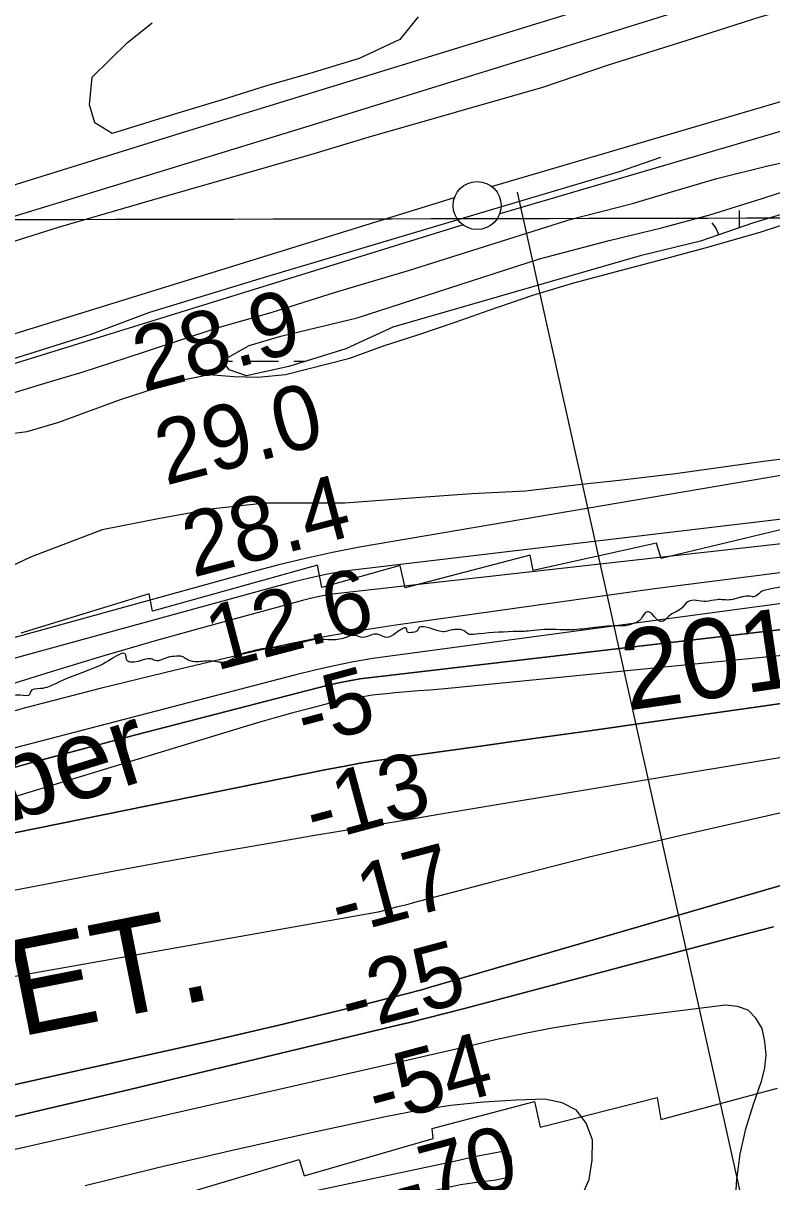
# Model space of a CAD drawing. Extents: x 3324104 to 3361979, y 612876 to 638273.
# Drawn here: x 3358506 to 3359286, y 623368 to 624575 of the extents above; entities that cross this region are included whole.
import ezdxf

# ---------------------------------------------------------------- set-up
doc = ezdxf.new("R2010")
doc.units = 0
for name, color, linetype in [('V-FLOD-BASE', 7, 'Continuous'), ('V-GRID-MAJR', 7, 'Continuous'), ('V-LEVE-TOET', 7, 'Continuous'), ('V-RIVR-EDGE', 7, 'Continuous'), ('V-RIVR-IDEN', 7, 'Continuous'), ('V-RIVR-RANG', 7, 'Continuous'), ('V-ROAD-CNTR', 7, 'Continuous'), ('V-RRAP-RVMT', 7, 'Continuous'), ('V-RRAP-RVMT-IDEN', 7, 'Continuous'), ('V-SITE-VEGE', 7, 'Continuous'), ('V-SURV-LINE', 7, 'Continuous'), ('V-TOPO-DPTH', 7, 'Continuous'), ('V-TOPO-MAJR', 7, 'Continuous'), ('V-TOPO-MINR', 7, 'Continuous'), ('V-TOPO-SHOR', 7, 'Continuous'), ('V-TOPO-WATR', 7, 'Continuous'), ('V-WETL-SWMP', 7, 'Continuous')]:
    doc.layers.add(name, color=color, linetype=linetype)

msp = doc.modelspace()

# ---------------------------------------------------------------- linework, layer by layer
at = {"layer": 'V-FLOD-BASE'}
msp.add_lwpolyline([(3357573.7, 623938.3), (3357694.3, 623971.4), (3357787.7, 624000.3), (3357855.4, 624024.9), (3357917.4, 624046), (3358004.5, 624073.5), (3358209.5, 624137.6), (3358342.7, 624180.5), (3358480, 624220.7), (3358576.2, 624250.9), (3358637.5, 624274.1), (3358756.1, 624310.1), (3358978.5, 624376.3), (3359127, 624420.6), (3359170.2, 624435.4)], dxfattribs=at)
at = {"layer": 'V-GRID-MAJR'}
msp.add_spline([(3328210, 624318.2), (3333474, 624325.5), (3338738.1, 624333.5), (3344002.2, 624342.3), (3349266.2, 624351.9), (3354530.3, 624362.2), (3359794.3, 624373.3)], degree=3, dxfattribs=at)
at = {"layer": 'V-LEVE-TOET'}
for points in [[(3359793.5, 624738.8), (3359769, 624731.3), (3359688.9, 624701.1), (3359550.8, 624665.1), (3359476.2, 624641.2), (3359417.7, 624623.6), (3359352.1, 624603.8), (3359273.3, 624581.3), (3359196, 624556.7), (3359115.1, 624531.3), (3359046.8, 624508.1), (3358864.8, 624455.9), (3358808.3, 624439), (3358629.2, 624387.6), (3358542, 624362.2), (3358457, 624335.5), (3358284.8, 624279.9), (3358184.4, 624245.4), (3358102.8, 624217.3), (3358017.1, 624190.5), (3357952.9, 624172.9), (3357881.1, 624150.3), (3357810.7, 624127.1)], [(3358479, 624185), (3358527.1, 624199.8), (3358568.2, 624211.8), (3358612.9, 624226.5), (3358635.2, 624233.6), (3358668.6, 624244.8), (3358707.7, 624257.5), (3358764.1, 624273.7), (3358831.1, 624294.8), (3358907, 624317.4), (3359076.5, 624370.9), (3359140.6, 624387.1), (3359177.6, 624398.4), (3359228.4, 624413.2), (3359281.4, 624426.6), (3359311.4, 624433)]]:
    msp.add_lwpolyline(points, dxfattribs=at)
at = {"layer": 'V-RIVR-EDGE'}
msp.add_spline([(3359795.1, 624016.8), (3359789.3, 624017.3), (3359775.9, 624016.6), (3359757.2, 624013.5), (3359746.3, 624008.2), (3359732.2, 624007.9), (3359730.4, 624010), (3359728, 624012.1), (3359719.2, 624015.3), (3359708.9, 624015), (3359699.4, 624012.9), (3359694.1, 624014), (3359689.9, 624019.3), (3359671.6, 624018.6), (3359656.8, 624018.7), (3359645.9, 624019.4), (3359641.6, 624018), (3359635.7, 624018), (3359629, 624018.7), (3359625.4, 624017.7), (3359622.6, 624015.9), (3359617.7, 624018.4), (3359614.2, 624018.1), (3359610.6, 624015.6), (3359604.6, 624013.9), (3359595.5, 624015.6), (3359584.6, 624016.7), (3359572.2, 624017.8), (3359546.5, 624016.5), (3359518.3, 624014.1), (3359492.9, 624011), (3359467.9, 624006.1), (3359449.9, 624003.7), (3359441.8, 624003.3), (3359440, 624000.2), (3359435.1, 623999.1), (3359430.9, 623999.1), (3359426.3, 624001.3), (3359420.7, 623999.9), (3359418.5, 623997.8), (3359412.9, 623997.8), (3359403.4, 623999.2), (3359387.5, 623996.8), (3359379.4, 623994.3), (3359374.1, 623986.6), (3359371.6, 623982.4), (3359366.3, 623980.3), (3359359.3, 623979.9), (3359344.8, 623973.3), (3359335, 623971.5), (3359325.1, 623970.1), (3359313.8, 623976.2), (3359306.4, 623982.2), (3359301.9, 623987.1), (3359291.3, 623986.8), (3359279.3, 623984.4), (3359273.7, 623981.9), (3359267, 623977.3), (3359261.3, 623978.1), (3359255.7, 623977.4), (3359251.1, 623976.3), (3359243, 623974.2), (3359228.6, 623974.3), (3359217.3, 623972.5), (3359198.2, 623972.2), (3359192.2, 623965.9), (3359178.1, 623956.8), (3359170.7, 623951.5), (3359167.5, 623952.6), (3359164.7, 623955), (3359158.4, 623961.4), (3359155.9, 623961.8), (3359149.6, 623954.4), (3359141.5, 623949.5), (3359136.2, 623947.7), (3359123.5, 623947), (3359098.5, 623945), (3359077.3, 623942.9), (3359044.5, 623943), (3359031.8, 623941.6), (3359016, 623941), (3358974.8, 623938.2), (3358969.1, 623938.6), (3358965.2, 623941.8), (3358956.8, 623943.2), (3358951.2, 623942.5), (3358945.9, 623941.1), (3358933.2, 623943.3), (3358922.3, 623946.1), (3358918, 623945.1), (3358916.6, 623942.3), (3358911.7, 623940.2), (3358905.7, 623941.2), (3358905.3, 623943.7), (3358894.1, 623939.9), (3358884.5, 623934.9), (3358876.4, 623937.8), (3358872.9, 623938.5), (3358859.5, 623935), (3358851.1, 623937.1), (3358839.1, 623934), (3358822.9, 623932.6), (3358809.8, 623932.7), (3358783.7, 623926), (3358762.2, 623924), (3358742.8, 623920.5), (3358726.3, 623914.5), (3358716.4, 623909.3), (3358700.9, 623910.4), (3358684.3, 623909.7), (3358675.2, 623912.6), (3358672, 623914.7), (3358662.8, 623915.1), (3358657.9, 623914.7), (3358643.1, 623910.9), (3358638.9, 623912.6), (3358635.7, 623912.7), (3358618.8, 623909.2), (3358613.5, 623911.3), (3358612.8, 623913.8), (3358612.1, 623917.3), (3358598, 623912.7), (3358575.4, 623901.5), (3358539.1, 623886.8), (3358523.6, 623881.6), (3358513, 623878.4), (3358512.6, 623876), (3358502.4, 623874.9), (3358488.3, 623871.4), (3358468.9, 623862.3), (3358449.5, 623848.6), (3358433.3, 623838.8), (3358414.2, 623829.7), (3358401.2, 623829), (3358394.5, 623831.1), (3358393.4, 623834.3), (3358394.1, 623838.9), (3358393.4, 623842.1), (3358391.7, 623843.1), (3358389.2, 623843.1), (3358388.9, 623837.9), (3358385.3, 623837.9), (3358382.9, 623833.3), (3358381.1, 623829.1), (3358377.9, 623826.3), (3358373, 623828), (3358366.6, 623827.7), (3358362.4, 623823.8), (3358357.4, 623818.9), (3358350, 623817.5), (3358338.4, 623811.9), (3358324.6, 623804.9), (3358314.1, 623802.8), (3358302.1, 623799), (3358298.9, 623793.7), (3358291.8, 623793.3), (3358284.4, 623793), (3358276, 623792.3), (3358270, 623787.4), (3358261.9, 623780), (3358253.4, 623777.2), (3358241.4, 623775.1), (3358222.7, 623771), (3358210.7, 623766.4), (3358198.7, 623761.9), (3358192, 623752), (3358185.7, 623745.3), (3358171.6, 623742.9), (3358161.7, 623736.2), (3358141.9, 623726.4), (3358128.5, 623723.3), (3358116.5, 623720.8), (3358097.5, 623717), (3358087.3, 623715.6), (3358076.7, 623714.2), (3358064.4, 623711.8), (3358053.1, 623709), (3358034, 623701.7), (3358000.5, 623685.5), (3357981.1, 623681.4), (3357961.4, 623677.9), (3357943.4, 623676.2), (3357922.6, 623674.1), (3357909.2, 623666.7), (3357896.5, 623659), (3357880.3, 623648.1), (3357868.3, 623637.2), (3357853.4, 623620), (3357846.7, 623608.4), (3357833.3, 623593.3), (3357819.5, 623579.2)], degree=3, dxfattribs=at)
at = {"layer": 'V-RIVR-RANG'}
msp.add_line((3359020.3, 624399.2), (3359276.9, 623247.4), dxfattribs=at)
at = {"layer": 'V-ROAD-CNTR'}
msp.add_lwpolyline([(3359791, 624815.2), (3359721.2, 624794.2), (3359118.5, 624598.3), (3358677.7, 624463), (3358086.3, 624278.8), (3357533.4, 624100.8), (3357044.6, 623937.5)], dxfattribs=at)
at = {"layer": 'V-RRAP-RVMT'}
for p, q in [((3359300.8, 624048.6), (3359170.3, 624017.4)), ((3359165.7, 624033.3), (3359036.9, 624004.8)), ((3359170.3, 624017.4), (3359165.7, 624033.3)), ((3359034, 624020.7), (3358903.7, 623986.6)), ((3359036.9, 624004.8), (3359034, 624020.7)), ((3358812.4, 624010.4), (3358640.4, 623962.2)), ((3358816.8, 623987.2), (3358812.4, 624010.4)), ((3358898.3, 624009.9), (3358816.8, 623987.2)), ((3358903.7, 623986.6), (3358898.3, 624009.9)), ((3358636.7, 623980.5), (3358503.2, 623939.3)), ((3358640.4, 623962.2), (3358636.7, 623980.5)), ((3359170.2, 623432.5), (3359291.6, 623465.3)), ((3358931.7, 623423.2), (3359038.5, 623451.3)), ((3359038.5, 623451.3), (3359044.2, 623424.7)), ((3359044.2, 623424.7), (3359166.3, 623455.6)), ((3359166.3, 623455.6), (3359170.2, 623432.5)), ((3358932.9, 623412.8), (3358931.7, 623423.2)), ((3358798.3, 623373.8), (3358932.9, 623412.8)), ((3358680.3, 623357.1), (3358793.2, 623391)), ((3358793.2, 623391), (3358798.3, 623373.8))]:
    msp.add_line(p, q, dxfattribs=at)
at = {"layer": 'V-SITE-VEGE'}
for p, q in [((3359273.7, 624357.4), (3359323.3, 624373.6)), ((3359216.4, 624341.1), (3359273.7, 624357.4)), ((3359167.4, 624327.7), (3359216.4, 624341.1)), ((3359129, 624317.8), (3359167.4, 624327.7)), ((3359079.4, 624304.4), (3359129, 624317.8)), ((3359036.8, 624291.7), (3359079.4, 624304.4)), ((3358991.3, 624276.2), (3359036.8, 624291.7)), ((3358955.7, 624263.5), (3358991.3, 624276.2)), ((3358918, 624250.8), (3358955.7, 624263.5)), ((3358880.9, 624238.8), (3358918, 624250.8)), ((3358846, 624226.1), (3358880.9, 624238.8)), ((3358778.9, 624209.1), (3358846, 624226.1)), ((3358667, 624202.5), (3358699.2, 624208.9)), ((3358699.2, 624208.9), (3358725.1, 624206.9)), ((3358725.1, 624206.9), (3358750.2, 624206.2)), ((3358750.2, 624206.2), (3358778.9, 624209.1)), ((3358606.9, 624182.8), (3358667, 624202.5)), ((3358542.6, 624159.5), (3358606.9, 624182.8)), ((3358509.8, 624149.6), (3358542.6, 624159.5)), ((3358432.2, 624140.3), (3358509.8, 624149.6)), ((3359333.1, 624125.4), (3359277.1, 624118.2)), ((3359277.1, 624118.2), (3359185.5, 624105.4)), ((3359129.6, 624098.9), (3359084.2, 624093.9)), ((3359185.5, 624105.4), (3359129.6, 624098.9)), ((3358973, 624084.5), (3358910.1, 624080.1)), ((3359028.9, 624087.4), (3358973, 624084.5)), ((3359084.2, 624093.9), (3359028.9, 624087.4)), ((3358757.6, 624074.8), (3358703.8, 624069)), ((3358840.8, 624075), (3358757.6, 624074.8)), ((3358910.1, 624080.1), (3358840.8, 624075)), ((3358703.8, 624069), (3358647.8, 624059.1)), ((3358647.8, 624059.1), (3358587.7, 624047)), ((3358587.7, 624047), (3358513, 624018.8)), ((3358513, 624018.8), (3358466.2, 623996.3))]:
    msp.add_line(p, q, dxfattribs=at)
msp.add_lwpolyline([(3358917, 624581.8), (3358898.2, 624558.1), (3358855.7, 624538.4), (3358807.6, 624523.6), (3358758.1, 624509.5), (3358712.8, 624495.4), (3358666.8, 624481.4), (3358598.4, 624460.2), (3358580.3, 624471.3), (3358574.6, 624490.2), (3358577.3, 624518.8), (3358614.2, 624555.2), (3358640, 624575.5)], dxfattribs=at)
at = {"layer": 'V-SURV-LINE'}
for points in [[(3358993.6, 624405.1), (3359793.8, 624640.4)], [(3359793.8, 624609.2), (3359002.1, 624376.4)], [(3358112.8, 624132.9), (3358955.1, 624393.5)], [(3358964, 624364.9), (3358121.7, 624104.3)]]:
    msp.add_lwpolyline(points, dxfattribs=at)
msp.add_circle((3358978.6, 624385.1), 25, dxfattribs=at)
at = {"layer": 'V-TOPO-DPTH'}
for points in [[(3359795.1, 624002), (3359795, 624064.7), (3359704.9, 624052.9), (3359677.3, 624049.3), (3359649.7, 624045.9), (3359622.1, 624042.6), (3359594.5, 624039.3), (3359487.4, 624027.1), (3359163.3, 623985.8), (3358894, 623947.9), (3358857.7, 623942.3), (3358821.4, 623936.1), (3358785.3, 623928.8), (3358749.3, 623920.9), (3358664.1, 623901), (3358585.8, 623881.8), (3358507.8, 623861.6), (3358430.3, 623839.8)], [(3358412.2, 623776.3), (3358517.4, 623805.4), (3358622.8, 623833.5), (3358812.6, 623882.5), (3358823.5, 623885.2), (3358834.4, 623887.6), (3358845.3, 623889.8), (3358856.3, 623891.8), (3359563.8, 623974.6), (3359588.7, 623977.3), (3359613.5, 623980.1), (3359646.5, 623983.9), (3359654.9, 623984.9), (3359663.3, 623985.9), (3359671.6, 623986.9), (3359680, 623987.9), (3359795.1, 624002)], [(3358412.2, 623776.3), (3358517.4, 623805.4), (3358622.8, 623833.5), (3358812.6, 623882.5), (3358823.5, 623885.2), (3358834.4, 623887.6), (3358845.3, 623889.8), (3358856.3, 623891.8), (3359563.8, 623974.6), (3359588.7, 623977.3), (3359613.5, 623980.1), (3359646.5, 623983.9), (3359654.9, 623984.9), (3359663.3, 623985.9), (3359671.6, 623986.9), (3359680, 623987.9), (3359795.1, 624002)], [(3359795.1, 624002), (3359795.3, 623935.2), (3359780.5, 623933.5), (3359754.9, 623930.4), (3359729.3, 623927.1), (3359693.8, 623922.4), (3359686, 623921.4), (3359678.1, 623920.3), (3359670.2, 623919.2), (3359662.4, 623918.1), (3359158.6, 623846.6), (3359098.2, 623838.1), (3359037.8, 623829.6), (3358977.4, 623821.1), (3358891.8, 623809.2), (3358874.2, 623806.6), (3358856.6, 623803.8), (3358839.1, 623800.6), (3358821.6, 623797.2), (3358450, 623721.8)], [(3358450, 623721.8), (3358821.6, 623797.2), (3358839.1, 623800.6), (3358856.6, 623803.8), (3358874.2, 623806.6), (3358891.8, 623809.2), (3358977.4, 623821.1), (3359037.8, 623829.6), (3359098.2, 623838.1), (3359158.6, 623846.6), (3359662.4, 623918.1), (3359670.2, 623919.2), (3359678.1, 623920.3), (3359686, 623921.4), (3359693.8, 623922.4), (3359729.3, 623927.1), (3359754.9, 623930.4), (3359780.5, 623933.5), (3359795.3, 623935.2), (3359795.5, 623861.1)], [(3359795.5, 623861.1), (3359731.4, 623849.4), (3359713.5, 623846), (3359695.7, 623842.4), (3359677.9, 623838.7), (3359660.1, 623834.8), (3359194.2, 623729.2), (3359144, 623717.5), (3359093.9, 623705.5), (3359043.9, 623692.9), (3358994, 623680), (3358913.5, 623658.7), (3358903.9, 623656.1), (3358894.4, 623653.7), (3358884.8, 623651.2), (3358875.3, 623648.8), (3358126, 623516.1)], [(3359795.5, 623861.1), (3359731.4, 623849.4), (3359713.5, 623846), (3359695.7, 623842.4), (3359677.9, 623838.7), (3359660.1, 623834.8), (3359194.2, 623729.2), (3359144, 623717.5), (3359093.9, 623705.5), (3359043.9, 623692.9), (3358994, 623680), (3358913.5, 623658.7), (3358903.9, 623656.1), (3358894.4, 623653.7), (3358884.8, 623651.2), (3358875.3, 623648.8), (3358126, 623516.1)], [(3358072.6, 623374.6), (3358704.8, 623515.3), (3358740.7, 623523.5), (3358776.6, 623531.8), (3358812.4, 623540.5), (3358848.1, 623549.4), (3358910.3, 623565.1), (3358914.9, 623566.3), (3358919.5, 623567.5), (3358924, 623568.8), (3358928.6, 623570.1), (3359598.2, 623764.2)], [(3358072.6, 623374.6), (3358704.8, 623515.3), (3358740.7, 623523.5), (3358776.6, 623531.8), (3358812.4, 623540.5), (3358848.1, 623549.4), (3358910.3, 623565.1), (3358914.9, 623566.3), (3358919.5, 623567.5), (3358924, 623568.8), (3358928.6, 623570.1), (3359598.2, 623764.2)], [(3359287.4, 623633.2), (3359253.8, 623624.8), (3358965.5, 623548.4), (3358946.4, 623543.4), (3358927.2, 623538.5), (3358908, 623533.7), (3358888.7, 623529.1), (3358616.7, 623464), (3358522.9, 623441.8), (3358429, 623419.8)], [(3358429, 623419.8), (3358522.9, 623441.8), (3358616.7, 623464), (3358888.7, 623529.1), (3358908, 623533.7), (3358927.2, 623538.5), (3358946.4, 623543.4), (3358965.5, 623548.4), (3359253.8, 623624.8), (3359287.4, 623633.2)]]:
    msp.add_lwpolyline(points, dxfattribs=at)
at = {"layer": 'V-TOPO-MAJR'}
for points in [[(3359585.2, 624153), (3358855.9, 624029.1), (3358827.8, 624023.5), (3358799.9, 624017.4), (3358772.1, 624010.5), (3358744.4, 624003.3), (3358016.3, 623802.3)], [(3359247.6, 623343.1), (3359249.3, 623370), (3359252.8, 623396.6), (3359258.8, 623422.8), (3359266.5, 623448.6), (3359275, 623472.4), (3359278.3, 623486.1), (3359279.8, 623499.9), (3359278.6, 623513.7), (3359275.6, 623527.5), (3359269.1, 623538.3), (3359260.9, 623546.4), (3359250.1, 623550.4), (3359237.6, 623551.6), (3359120.5, 623537.3), (3359089.6, 623533), (3359058.9, 623528.1), (3359028.3, 623522.1), (3358997.8, 623515.5), (3358967.4, 623508.4), (3358937.1, 623501.4), (3358906.7, 623494.4), (3358876.2, 623487.5), (3358088.9, 623308.7)]]:
    msp.add_lwpolyline(points, dxfattribs=at)
at = {"layer": 'V-TOPO-MINR'}
for points in [[(3359794.9, 624093.1), (3359672.5, 624075.8), (3359658.2, 624073.8), (3359643.8, 624071.9), (3359629.5, 624070.1), (3359615.1, 624068.4), (3358824.9, 623979.8), (3358817.8, 623978.4), (3358810.7, 623976.9), (3358803.6, 623975.2), (3358796.6, 623973.4), (3358699.8, 623947.1), (3358644.6, 623931.8), (3358589.5, 623915.9), (3358534.6, 623899.3), (3358479.8, 623882.2), (3357966.8, 623718.6), (3357954, 623714.4), (3357941.2, 623710.1), (3357928.5, 623705.8), (3357915.8, 623701.3), (3357248, 623461.7)], [(3359594.4, 624093.6), (3358840.4, 624004.2), (3358822.8, 624000.8), (3358805.3, 623997.1), (3358787.8, 623992.9), (3358770.4, 623988.4), (3358452.4, 623901.3)], [(3359795, 624064.7), (3359704.9, 624052.9), (3359677.3, 624049.3), (3359649.7, 624045.9), (3359622.1, 624042.6), (3359594.5, 624039.3), (3359487.4, 624027.1), (3359163.3, 623985.8), (3358894, 623947.9), (3358857.7, 623942.3), (3358821.4, 623936.1), (3358785.3, 623928.8), (3358749.3, 623920.9), (3358664.1, 623901), (3358585.8, 623881.8), (3358507.8, 623861.6), (3358430.3, 623839.8)], [(3359795.1, 624036.4), (3359737.8, 624029.3), (3359696.7, 624024.3), (3358870, 623913.1), (3358849.8, 623909.4), (3358829.6, 623905.4), (3358809.6, 623900.8), (3358789.6, 623895.9), (3358137.7, 623726.6), (3358106.6, 623718.2), (3358075.7, 623709.6), (3358044.8, 623700.4), (3358014.1, 623690.9), (3357983.5, 623681), (3357953, 623670.8), (3357922.6, 623660.3), (3357892.3, 623649.4), (3357881.3, 623645.4), (3357845.6, 623632.3), (3357809.9, 623618.9), (3357774.4, 623605.4), (3357738.9, 623591.6), (3357198, 623379.8)], [(3359795.2, 623967.6), (3359722.4, 623958.3), (3358941.5, 623881.2), (3358929.4, 623880.2), (3358917.4, 623879.2), (3358905.3, 623878.2), (3358893.2, 623877.1), (3358884.1, 623876.3), (3358876.6, 623875.6), (3358869.1, 623874.7), (3358861.5, 623873.6), (3358854, 623872.5), (3358842.6, 623870.5), (3358839.1, 623869.9), (3358837.4, 623869.5), (3358835.6, 623869.1), (3358804.1, 623861), (3358786.7, 623856.4), (3358769.3, 623851.6), (3358752, 623846.7), (3358734.7, 623841.5), (3357991.5, 623614.9)], [(3359795.3, 623935.2), (3359780.5, 623933.5), (3359754.9, 623930.4), (3359729.3, 623927.1), (3359693.8, 623922.4), (3359686, 623921.4), (3359678.1, 623920.3), (3359670.2, 623919.2), (3359662.4, 623918.1), (3359158.6, 623846.6), (3359098.2, 623838.1), (3359037.8, 623829.6), (3358977.4, 623821.1), (3358891.8, 623809.2), (3358874.2, 623806.6), (3358856.6, 623803.8), (3358839.1, 623800.6), (3358821.6, 623797.2), (3358450, 623721.8)], [(3359795.4, 623892.6), (3359757.8, 623886.8), (3359723, 623881.4), (3359688.1, 623875.8), (3359653.3, 623870.1), (3359618.5, 623864.3), (3359563.5, 623854.9), (3359501.3, 623844.4), (3359439, 623833.8), (3359376.7, 623823.4), (3359314.4, 623813), (3358940.7, 623750.7), (3358906.8, 623745), (3358873, 623739.3), (3358839.1, 623733.5), (3358805.2, 623727.7), (3358764, 623720.7), (3358709.5, 623711.2), (3358655.1, 623701.4), (3358600.7, 623691.4), (3358546.4, 623681.1), (3358045.3, 623584.8)], [(3359795.5, 623861.1), (3359731.4, 623849.4), (3359713.5, 623846), (3359695.7, 623842.4), (3359677.9, 623838.7), (3359660.1, 623834.8), (3359194.2, 623729.2), (3359144, 623717.5), (3359093.9, 623705.5), (3359043.9, 623692.9), (3358994, 623680), (3358913.5, 623658.7), (3358903.9, 623656.1), (3358894.4, 623653.7), (3358884.8, 623651.2), (3358875.3, 623648.8), (3358126, 623516.1)], [(3359598.2, 623764.2), (3358928.6, 623570.1), (3358924, 623568.8), (3358919.5, 623567.5), (3358914.9, 623566.3), (3358910.3, 623565.1), (3358848.1, 623549.4), (3358812.4, 623540.5), (3358776.6, 623531.8), (3358740.7, 623523.5), (3358704.8, 623515.3), (3358072.6, 623374.6)], [(3359287.4, 623633.2), (3359253.8, 623624.8), (3358965.5, 623548.4), (3358946.4, 623543.4), (3358927.2, 623538.5), (3358908, 623533.7), (3358888.7, 623529.1), (3358616.7, 623464), (3358522.9, 623441.8), (3358429, 623419.8)], [(3359087, 623351.3), (3359095.2, 623370), (3359098.6, 623390.2), (3359098.7, 623411.3), (3359092.1, 623428.7), (3359082.1, 623442.2), (3359067.3, 623449.9), (3359049.1, 623453.7), (3359019.8, 623452.6), (3358985.4, 623450.5), (3358951.1, 623447.1), (3358917, 623441.9), (3358883.1, 623435.5), (3358798, 623417), (3358721.8, 623400), (3358645.7, 623382.2), (3358570, 623363.3)]]:
    msp.add_lwpolyline(points, dxfattribs=at)
msp.add_lwpolyline([(3358090.9, 623205), (3358091.8, 623205.2), (3358091.9, 623205.2), (3358712.8, 623313.7), (3358756.4, 623321.6), (3358799.8, 623329.9), (3358843.1, 623338.8), (3358886.3, 623348.1), (3358961.1, 623364.7), (3358983, 623368), (3358995.9, 623369.3), (3359011.5, 623372.4), (3359013.8, 623378.2), (3359014.5, 623389.8), (3359013.8, 623394.6), (3359005.3, 623399.2), (3358973.7, 623393.4), (3358959.6, 623389.9), (3358092.3, 623205.6), (3358092.2, 623205.5), (3358091.9, 623205.5), (3358090.8, 623205.1)], close=True, dxfattribs=at)
at = {"layer": 'V-TOPO-SHOR'}
msp.add_lwpolyline([(3355996.4, 623451.8), (3356155, 623531.3), (3356400.8, 623643.9), (3356613.2, 623742.4), (3356803.9, 623822.7), (3356903.1, 623858), (3357072.9, 623915.8), (3357254.5, 623979.2), (3357418.8, 624030.1), (3357740.2, 624135.2), (3357945.6, 624198.7), (3358188.8, 624279.8), (3358327.1, 624320.8), (3358476.7, 624368), (3358599.7, 624405.5), (3358803.7, 624468.3), (3359039.2, 624541), (3359236.3, 624603.1), (3359396.3, 624653.2), (3359557, 624703.3), (3359692.6, 624749.1), (3359793.4, 624782.9)], dxfattribs=at)
at = {"layer": 'V-TOPO-WATR'}
msp.add_lwpolyline([(3359795.1, 624002), (3359680, 623987.9), (3359671.6, 623986.9), (3359663.3, 623985.9), (3359654.9, 623984.9), (3359646.5, 623983.9), (3359613.5, 623980.1), (3359588.7, 623977.3), (3359563.8, 623974.6), (3358856.3, 623891.8), (3358845.3, 623889.8), (3358834.4, 623887.6), (3358823.5, 623885.2), (3358812.6, 623882.5), (3358622.8, 623833.5), (3358517.4, 623805.4), (3358412.2, 623776.3)], dxfattribs=at)
at = {"layer": 'V-WETL-SWMP'}
for p, q in [((3359275.7, 624392.4), (3359325.3, 624408.6)), ((3359221.2, 624375.4), (3359275.7, 624392.4)), ((3359170.8, 624362), (3359221.2, 624375.4)), ((3359252, 624362.1), (3359252, 624379.8)), ((3359326, 624384.8), (3359266.6, 624367.2)), ((3359266.6, 624367.2), (3359211.4, 624348.1)), ((3359116.3, 624348.6), (3359170.8, 624362)), ((3359043.6, 624329.5), (3359116.3, 624348.6)), ((3359211.4, 624348.1), (3359148.5, 624332.6)), ((3358853.6, 624268.1), (3359043.6, 624329.5)), ((3359148.5, 624332.6), (3358890.7, 624258.4)), ((3358773.9, 624249), (3358853.6, 624268.1)), ((3358890.7, 624258.4), (3358841.8, 624235.9)), ((3358741.1, 624239.1), (3358773.9, 624249)), ((3358713.1, 624223.6), (3358741.1, 624239.1)), ((3358841.8, 624235.9), (3358782.4, 624217.5)), ((3358720.1, 624213.9), (3358713.1, 624223.6)), ((3358713.7, 624222.8), (3358723.5, 624222.8)), ((3358782.4, 624217.5), (3358738.3, 624207.6)), ((3358739.5, 624222.8), (3358771.5, 624222.9)), ((3358787.5, 624222.9), (3358799.9, 624222.9)), ((3358738.3, 624207.6), (3358720.1, 624213.9))]:
    msp.add_line(p, q, dxfattribs=at)
msp.add_arc((3359196.8, 624344.2), 35.2, 17.3566, 40.8718, dxfattribs=at)

# ---------------------------------------------------------------- texts
at = {"layer": 'V-RIVR-IDEN'}
for s, rotation, p in [(' 2012', 8.3852, (3359105, 623854.2)), ('September', 17.2412, (3358124.5, 623628.2))]:
    msp.add_text(s, height=83, rotation=rotation, dxfattribs=at).set_placement(p)
at = {"layer": 'V-RIVR-RANG'}
for s, rotation, p in [('28.9', 14.7483, (3358630.7, 624190.4)), ('29.0', 14.7483, (3358653.9, 624093.1)), ('28.4', 14.7483, (3358682.4, 623997.2)), ('12.6', 14.7483, (3358706.3, 623900.1)), ('-5', 15.0271, (3358799.5, 623820.9)), ('-13', 15.0271, (3358808.9, 623719.9)), ('-17', 15.0271, (3358835.1, 623623.4)), ('-25', 15.0271, (3358845.5, 623522.7)), ('-54', 15.0271, (3358874, 623426.8)), ('-70', 15.0271, (3358900.2, 623330.3))]:
    msp.add_text(s, height=67, rotation=rotation, dxfattribs=at).set_placement(p)
at = {"layer": 'V-RRAP-RVMT-IDEN'}
msp.add_text('REVET.', height=100, rotation=11.1885, dxfattribs=at).set_placement((3358231.9, 623465.3))

doc.saveas('drawing.dxf')
